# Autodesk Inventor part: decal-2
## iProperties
Shininess: 64.0
Length Units: 11269
Angle Units: 11279
Time Units: 11290
Mass Units: 11283
Length Display Precision: 3
Angle Display Precision: 2
Compacted: True
Part Number: decal-2
Document SubType Name: Modeling
Created: 2002-12
Designer: deepak
Density: 0.0
Volumn: 0.0
Area: 0.0
PropertySet Name: Model Information
Control State: 0
Master: False
Checked Out: False
Author: deepak
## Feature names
1. Revolution1
2. Fillet1
3. Chamfer1
